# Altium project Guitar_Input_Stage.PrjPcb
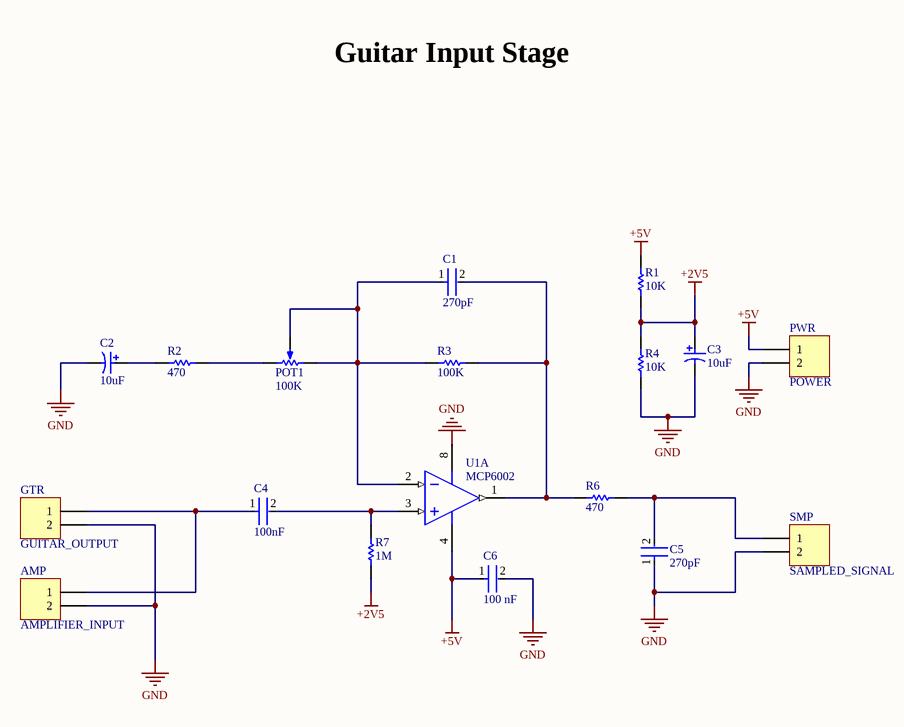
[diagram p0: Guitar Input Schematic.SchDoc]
1 sheet, 18 parts. Net scope: global (net labels, ports and power ports of the same name join across sheets).
Board file: Guitar Input PCB.PcbDoc

## Sheet Guitar Input Schematic.SchDoc
size A; SheetNumber: 1; SheetTotal: 1

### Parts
AMP  AMPLIFIER_INPUT  [HDR1X2]
C1  270pF  [FP-C0805C-DN-MFG]
C2  10uF  [KEMT-A-3216-18-2_M]
C3  10uF  [KEMT-A-3216-18-2_M]
C4  100nF  [FP-C0805C-DN-MFG]
C5  270pF  [FP-C0805C-DN-MFG]
C6  100 nF  [FP-C0805C-DN-MFG]
GTR  GUITAR_OUTPUT  [HDR1X2]
POT1  100K  [BOUR-3362P]
PWR  POWER  [HDR1X2]
R1  10K  [RESC2013X60X35NL10T20]
R2  470  [RESC2013X70X40ML20T20]
R3  100K  [RESC2013X60X35ML10T20]
R4  10K  [RESC2013X60X35NL10T20]
R6  470  [RESC2013X70X40ML20T20]
R7  1M  [RESC2013X70X40NL20T20]
SMP  SAMPLED_SIGNAL  [HDR1X2]
U1  MCP6002  [SOIC-SN8_M]  (part A of 2)

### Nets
+2V5: C3.1 R1.1 R4.2 R7.1
+5V: C6.1 PWR.1 R1.2 U1.4(VSS)
GND: AMP.2 C2.2 C3.2 C5.1 C6.2 GTR.2 PWR.2 R4.1 SMP.2 U1.8(VDD)
NetAMP_1: AMP.1 C4.1 GTR.1
NetC1_1: C1.1 POT1.1(CCW) POT1.2(S) R3.1 U1.2(VINA-)
NetC1_2: C1.2 R3.2 R6.1 U1.1(VOUTA)
NetC2_1: C2.1 R2.1
NetC4_2: C4.2 R7.2 U1.3(VINA+)
NetC5_2: C5.2 R6.2 SMP.1
NetPOT1_3: POT1.3(CW) R2.2

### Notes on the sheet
- Guitar Input Stage

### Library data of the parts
AMP GTR PWR SMP = Header 2: Header, 2-Pin
C1 C5 = CMP-1036-02406-3: CAP CER 270PF 50V C0G/NP0 0805; Manufacturer: KEMET; Manufacturer Part Number: C0805C271J5GACTU; Material: Ceramic; Temperature Characteristic: C0G; Temperature Coefficient: 30ppm/°C; Description: C0805 270 pF C0G 30ppm/°C 5.00% 50 V; Tolerance: 0.05
C2 C3 = CMP-2000-05172-1: Capacitor, Tantalum, 10 uF, +/- 10%, 10 V, -55 to 125 degC, 2-Pin SMD (1206), RoHS, Tape and Reel; Manufacturer Size Code: A; Manufacturer: Kemet; Type: Molded; Online Catalog: T491Series; Other Names: 399-3684-2; Voltage - Rated: 10V; Lifetime @ Temp.: 2000Hrs@85degC; Product Training Modules: CapacitorBasics-TypicalUsesforCapacitorsDeratingGuidelinesforSurfaceMountTantalumCapacitors; ESR (Equivalent Series Resistance): 3.8Ohm; Capacitance: 10µF; Catalog Drawings: T49x,T5xxSeries_A-side1T49x,T5xxSeries_A,B-side2T49x,T5xxSeries_A,SBottom
C4 C6 = CMP-2007-00279-2: CAP CER 0.1UF 50V X7R 0805; Manufacturer Part Number: C0805C104K5RACTU; Manufacturer: KEMET; Value: 0.10 μF; Description: C0805 0.10 μF X7R 30ppm/°C 10.00% 50 V; Tolerance: 0.1; Temperature Coefficient: 30ppm/°C; Material: Ceramic
POT1 = CMP-1747-00003-1: Square Trimpot(R) Trimming Potentiometer, 100 KOhm, 300 V, -55 to 125 degC, 3-Pin THD, RoHS, Tube; Voltage Rating: 250 V; Case\Package: Axial; Tolerance: 1%; Power Rating: 250 mW; Resistance: 1 mohm
R1 R4 = CMP-1659-00013-4: Chip Resistor, 10 KOhm, +/- 1%, 0.125 W, -55 to 155 degC, 0805 (2012 Metric), RoHS, Tape and Reel; Manufacturer: Yageo; Voltage Rating: 150 V
R2 R6 = CMP-2001-00549-5: Chip Resistor, 470 Ohm, +/- 1%, 0.125 W, -55 to 155 degC, 0805 (2012 Metric), RoHS, Tape and Reel; Manufacturer: Panasonic; Voltage Rating: 150 V
R3 = CMP-2100-03668-1: Chip Resistor, 100 KOhm, +/- 1%, 0.125 W, -55 to 155 degC, 0805 (2012 Metric), RoHS, Tape and Reel; Manufacturer: Yageo; Max Power Dissipation: 125mW; Voltage Rating: 150V; Temperature Coefficient: 100ppm/degreesC
R7 = CMP-2001-04378-5: Chip Resistor, 1000 KOhm, +/- 1%, 0.125 W, -55 to 155 degC, 0805 (2012 Metric), RoHS, Tape and Reel; Manufacturer: Panasonic; Voltage Rating: 150 V
U1 = CMP-0187-00365-2: 1 MHz, Low-Power Operational Amplifier, 8-Pin SOIC, Industrial Temperature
